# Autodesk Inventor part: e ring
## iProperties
Author: rmjbm2
Shininess: 70.0
PropertySet Name: _Private Model Information
Created: 2001-01
Part Number: e ring
Document SubType Name: Modeling
Designer: rmjbm2
Control State: 0
Master: False
Checked Out: False
PropertySet Name: Design Tracking Control
Density: 0.0
Volumn: 0.0
Area: 0.0
PropertySet Name: Model Information
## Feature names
1. Extrusion4
